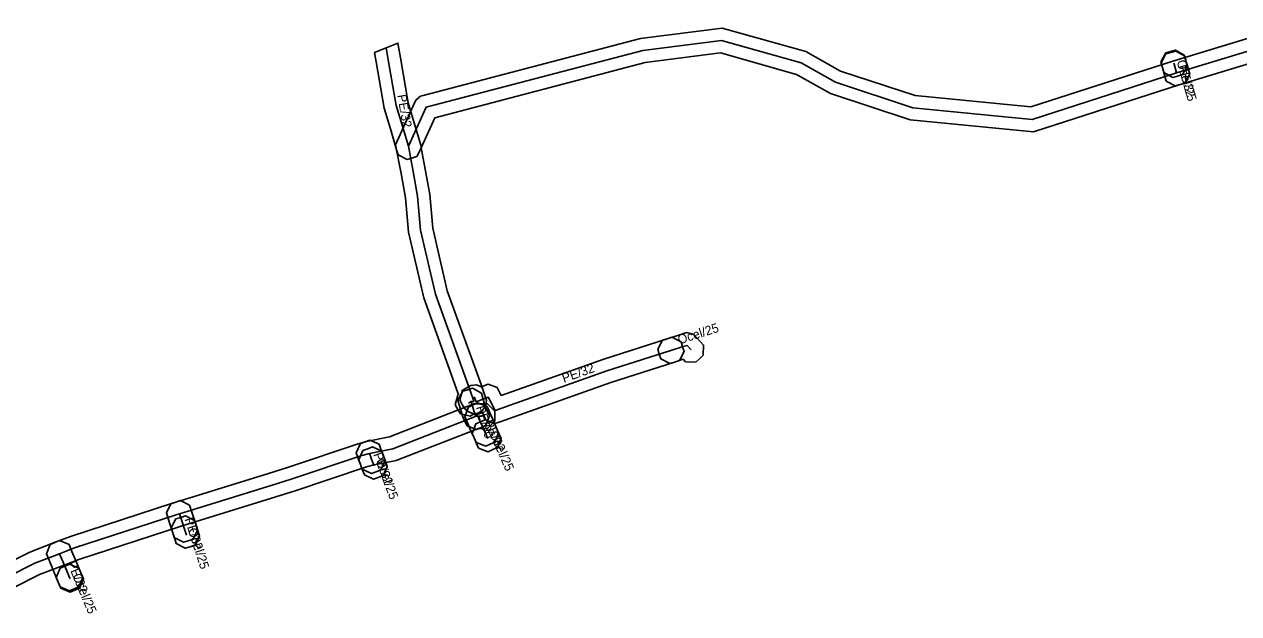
# Model space of a CAD drawing. Extents: x -677728 to -676939, y -1057290 to -1056960.
# Drawn here: x -677335.3 to -677236.2, y -1057106.7 to -1057058.6 of the extents above; entities that cross this region are included whole.
import ezdxf

# ---------------------------------------------------------------- set-up
doc = ezdxf.new("R2010")
doc.units = 0
for name, color, linetype in [('1', 7, 'Continuous'), ('24', 7, 'Continuous'), ('30', 7, 'Continuous')]:
    doc.layers.add(name, color=color, linetype=linetype)

msp = doc.modelspace()

# ---------------------------------------------------------------- linework, layer by layer
at = {"layer": '1'}
for points in [[(-677231.023, -1057060.492), (-677240.972, -1057063.495), (-677252.951, -1057067.366), (-677263.018, -1057066.374), (-677269.515, -1057064.24), (-677272.306, -1057062.67), (-677278.515, -1057060.928), (-677284.649, -1057061.714), (-677301.827, -1057066.207), (-677302.948, -1057068.666), (-677302.617, -1057070.408), (-677302.248, -1057072.467), (-677302, -1057075.232), (-677300.819, -1057080.327), (-677298.059, -1057087.981), (-677297.773, -1057088.779), (-677297.688, -1057089.045), (-677297.617, -1057089.268), (-677297.686, -1057089.73), (-677297.82, -1057089.922), (-677297.953, -1057090.114), (-677298.363, -1057090.339), (-677298.576, -1057090.348), (-677298.581, -1057090.351), (-677298.938, -1057090.562), (-677299.74, -1057090.356), (-677299.951, -1057089.999), (-677300.162, -1057089.642), (-677299.956, -1057088.84), (-677299.89, -1057088.801), (-677299.941, -1057088.659), (-677302.741, -1057080.893), (-677303.98, -1057075.548), (-677304.232, -1057072.733), (-677304.583, -1057070.772), (-677305.032, -1057068.414), (-677303.45, -1057064.945), (-677303.357, -1057064.74), (-677303.011, -1057064.45), (-677302.793, -1057064.393), (-677285.031, -1057059.746), (-677278.365, -1057058.892), (-677271.534, -1057060.81), (-677268.705, -1057062.4), (-677262.602, -1057064.406), (-677253.169, -1057065.334), (-677241.568, -1057061.585), (-677231.637, -1057058.588)], [(-677337.06, -1057102.732), (-677334.905, -1057101.644), (-677332.818, -1057100.846), (-677331.573, -1057100.367), (-677323.168, -1057097.639), (-677322.977, -1057097.577), (-677321.569, -1057097.126), (-677315.406, -1057095.225), (-677313.857, -1057094.738), (-677308.079, -1057092.816), (-677307.41, -1057092.618), (-677305.541, -1057092.246), (-677298.648, -1057089.56), (-677298.31, -1057089.56), (-677297.94, -1057089.56), (-677297.526, -1057089.56), (-677296.94, -1057090.146), (-677296.94, -1057090.56), (-677296.94, -1057090.974), (-677297.526, -1057091.56), (-677297.94, -1057091.56), (-677298.271, -1057091.56), (-677304.979, -1057094.174), (-677306.93, -1057094.562), (-677307.479, -1057094.724), (-677313.241, -1057096.642), (-677314.812, -1057097.135), (-677320.969, -1057099.034), (-677322.365, -1057099.481), (-677322.552, -1057099.541), (-677330.905, -1057102.253), (-677332.102, -1057102.714), (-677334.095, -1057103.476), (-677336.1, -1057104.488)]]:
    msp.add_lwpolyline(points, dxfattribs=at)
for points in [[(-677306.745, -1057060.884), (-677304.845, -1057060.124), (-677304.644, -1057061.323), (-677304.015, -1057064.981), (-677303.547, -1057066.538), (-677303.032, -1057068.252), (-677302.913, -1057068.649), (-677303.306, -1057069.379), (-677303.702, -1057069.498), (-677304.099, -1057069.617), (-677304.829, -1057069.224), (-677304.948, -1057068.828), (-677305.463, -1057067.114), (-677305.965, -1057065.439), (-677306.616, -1057061.657)], [(-677242.317, -1057062.521), (-677242.431, -1057062.123), (-677242.453, -1057062.046), (-677242.566, -1057061.648), (-677242.164, -1057060.923), (-677241.766, -1057060.809), (-677241.368, -1057060.696), (-677240.643, -1057061.098), (-677240.529, -1057061.496), (-677240.507, -1057061.573), (-677240.394, -1057061.971), (-677240.796, -1057062.696), (-677241.194, -1057062.81), (-677241.592, -1057062.923)], [(-677242.117, -1057063.214), (-677242.231, -1057062.816), (-677242.381, -1057062.295), (-677242.43, -1057062.125), (-677242.545, -1057061.727), (-677242.144, -1057061.002), (-677241.746, -1057060.887), (-677241.348, -1057060.772), (-677240.623, -1057061.173), (-677240.508, -1057061.571), (-677240.459, -1057061.741), (-677240.309, -1057062.264), (-677240.195, -1057062.662), (-677240.596, -1057063.387), (-677240.994, -1057063.501), (-677241.392, -1057063.615)], [(-677281.356, -1057086.123), (-677281.546, -1057085.919), (-677282.252, -1057086.145), (-677282.646, -1057086.271), (-677283.383, -1057085.892), (-677283.509, -1057085.498), (-677283.635, -1057085.104), (-677283.256, -1057084.367), (-677282.862, -1057084.241), (-677281.841, -1057083.914), (-677281.52, -1057083.82), (-677281.248, -1057083.741), (-677280.701, -1057083.892), (-677280.508, -1057084.099), (-677280.174, -1057084.458), (-677279.892, -1057084.761), (-677279.922, -1057085.589), (-677280.225, -1057085.871), (-677280.528, -1057086.153)], [(-677299.253, -1057090.121), (-677299.303, -1057089.978), (-677299.383, -1057089.956), (-677299.588, -1057089.596), (-677299.793, -1057089.236), (-677299.576, -1057088.437), (-677299.216, -1057088.232), (-677299.076, -1057088.152), (-677298.883, -1057088.041), (-677298.439, -1057088.005), (-677298.231, -1057088.083), (-677298.034, -1057088.156), (-677297.832, -1057088.078), (-677297.474, -1057087.939), (-677296.755, -1057088.212), (-677296.58, -1057088.554), (-677296.451, -1057088.805), (-677296.42, -1057088.866), (-677288.11, -1057085.922), (-677282.862, -1057084.241), (-677282.468, -1057084.115), (-677281.731, -1057084.494), (-677281.605, -1057084.888), (-677281.479, -1057085.282), (-677281.858, -1057086.019), (-677282.252, -1057086.145), (-677287.47, -1057087.818), (-677296.576, -1057091.043), (-677296.93, -1057091.168), (-677297.628, -1057090.891), (-677297.799, -1057090.557), (-677297.948, -1057090.268), (-677298.088, -1057090.322), (-677298.483, -1057090.476), (-677298.868, -1057090.298)], [(-677298.024, -1057088.684), (-677297.909, -1057089.082), (-677297.69, -1057089.84), (-677297.551, -1057090.142), (-677297.378, -1057090.519), (-677297.666, -1057091.296), (-677298.042, -1057091.469), (-677298.419, -1057091.642), (-677299.196, -1057091.354), (-677299.369, -1057090.978), (-677299.57, -1057090.54), (-677299.831, -1057089.638), (-677299.946, -1057089.24), (-677299.546, -1057088.514), (-677299.148, -1057088.399), (-677298.75, -1057088.284)], [(-677298.452, -1057092.715), (-677298.619, -1057092.336), (-677298.881, -1057091.742), (-677299.225, -1057090.964), (-677299.392, -1057090.585), (-677299.093, -1057089.813), (-677298.714, -1057089.645), (-677298.335, -1057089.478), (-677297.563, -1057089.777), (-677297.395, -1057090.156), (-677297.051, -1057090.934), (-677296.789, -1057091.528), (-677296.622, -1057091.907), (-677296.921, -1057092.68), (-677297.3, -1057092.847), (-677297.679, -1057093.014)], [(-677296.957, -1057091.149), (-677296.789, -1057091.528), (-677296.594, -1057091.969), (-677296.427, -1057092.348), (-677296.726, -1057093.12), (-677297.105, -1057093.288), (-677297.484, -1057093.455), (-677298.256, -1057093.156), (-677298.424, -1057092.777), (-677298.619, -1057092.336), (-677298.786, -1057091.957), (-677298.487, -1057091.185), (-677298.108, -1057091.017), (-677297.729, -1057090.85)], [(-677307.757, -1057094.888), (-677307.9, -1057094.499), (-677308.024, -1057094.164), (-677308.108, -1057093.937), (-677308.252, -1057093.548), (-677307.906, -1057092.796), (-677307.517, -1057092.652), (-677307.128, -1057092.508), (-677306.376, -1057092.854), (-677306.232, -1057093.243), (-677306.148, -1057093.47), (-677306.024, -1057093.807), (-677305.881, -1057094.196), (-677306.227, -1057094.948), (-677306.616, -1057095.091), (-677307.005, -1057095.234)], [(-677306.168, -1057093.417), (-677306.024, -1057093.806), (-677305.854, -1057094.266), (-677305.71, -1057094.655), (-677306.056, -1057095.407), (-677306.445, -1057095.551), (-677306.834, -1057095.695), (-677307.586, -1057095.349), (-677307.73, -1057094.96), (-677307.9, -1057094.5), (-677308.044, -1057094.111), (-677307.698, -1057093.359), (-677307.309, -1057093.215), (-677306.92, -1057093.071)], [(-677323.098, -1057100.467), (-677323.225, -1057100.073), (-677323.411, -1057099.495), (-677323.623, -1057098.835), (-677323.75, -1057098.441), (-677323.371, -1057097.704), (-677322.977, -1057097.577), (-677322.583, -1057097.45), (-677321.846, -1057097.829), (-677321.719, -1057098.223), (-677321.507, -1057098.883), (-677321.321, -1057099.461), (-677321.194, -1057099.855), (-677321.573, -1057100.592), (-677321.967, -1057100.719), (-677322.361, -1057100.846)], [(-677321.447, -1057099.068), (-677321.321, -1057099.462), (-677321.164, -1057099.952), (-677321.038, -1057100.346), (-677321.417, -1057101.083), (-677321.811, -1057101.209), (-677322.205, -1057101.335), (-677322.942, -1057100.956), (-677323.068, -1057100.562), (-677323.225, -1057100.072), (-677323.351, -1057099.678), (-677322.972, -1057098.941), (-677322.578, -1057098.815), (-677322.184, -1057098.689)], [(-677332.414, -1057104.486), (-677332.574, -1057104.104), (-677332.957, -1057103.187), (-677333.383, -1057102.165), (-677333.542, -1057101.783), (-677333.227, -1057101.016), (-677332.845, -1057100.857), (-677332.463, -1057100.698), (-677331.696, -1057101.013), (-677331.537, -1057101.395), (-677331.111, -1057102.417), (-677330.728, -1057103.332), (-677330.569, -1057103.714), (-677330.883, -1057104.481), (-677331.265, -1057104.641), (-677331.647, -1057104.8)], [(-677330.889, -1057102.95), (-677330.729, -1057103.332), (-677330.685, -1057103.437), (-677330.525, -1057103.819), (-677330.839, -1057104.585), (-677331.221, -1057104.745), (-677331.603, -1057104.905), (-677332.369, -1057104.591), (-677332.529, -1057104.209), (-677332.573, -1057104.104), (-677332.733, -1057103.722), (-677332.419, -1057102.956), (-677332.037, -1057102.796), (-677331.655, -1057102.636)]]:
    msp.add_lwpolyline(points, close=True, dxfattribs=at)
at = {"layer": '24'}
for points in [[(-677299.09, -1057089.49), (-677298.87, -1057089.36), (-677298.64, -1057089.35), (-677298.72, -1057089.1), (-677299, -1057088.32), (-677301.78, -1057080.61), (-677302.99, -1057075.39), (-677303.24, -1057072.6), (-677303.6, -1057070.59), (-677303.99, -1057068.54), (-677302.54, -1057065.36), (-677284.84, -1057060.73), (-677278.44, -1057059.91), (-677271.92, -1057061.74), (-677269.11, -1057063.32), (-677262.81, -1057065.39), (-677253.06, -1057066.35), (-677241.27, -1057062.54), (-677231.33, -1057059.54)], [(-677303.99, -1057068.54), (-677304.505, -1057066.826), (-677304.99, -1057065.21), (-677305.63, -1057061.49), (-677305.795, -1057060.504)], [(-677241.469, -1057061.848), (-677241.491, -1057061.771)], [(-677241.27, -1057062.54), (-677241.42, -1057062.018), (-677241.469, -1057061.848)], [(-677282.557, -1057085.193), (-677281.549, -1057084.87), (-677281.24, -1057084.78), (-677280.906, -1057085.139)], [(-677298.72, -1057089.1), (-677298.58, -1057089.02), (-677298.45, -1057089.39), (-677297.47, -1057089.01), (-677297.341, -1057089.262), (-677296.91, -1057090.1), (-677287.79, -1057086.87), (-677282.557, -1057085.193)], [(-677298.87, -1057089.36), (-677298.63, -1057090.19), (-677298.46, -1057090.56)], [(-677297.94, -1057090.56), (-677298.31, -1057090.56), (-677298.46, -1057090.56), (-677305.26, -1057093.21), (-677307.17, -1057093.59), (-677307.779, -1057093.77), (-677313.549, -1057095.69), (-677315.109, -1057096.18), (-677321.269, -1057098.08), (-677322.671, -1057098.529), (-677322.86, -1057098.59), (-677331.239, -1057101.31), (-677332.46, -1057101.78), (-677334.5, -1057102.56), (-677336.58, -1057103.61), (-677339.86, -1057105.55), (-677342.04, -1057104.6), (-677352.76, -1057100.9), (-677356.08, -1057100.3), (-677360.81, -1057098.32), (-677366.69, -1057096.31), (-677378.49, -1057092.57), (-677382.416, -1057091.152)], [(-677297.704, -1057091.932), (-677297.966, -1057091.338), (-677298.31, -1057090.56)], [(-677297.704, -1057091.932), (-677297.509, -1057092.373)], [(-677306.962, -1057094.153), (-677307.086, -1057093.817), (-677307.17, -1057093.59)], [(-677306.962, -1057094.153), (-677306.792, -1057094.613)], [(-677322.273, -1057099.767), (-677322.459, -1057099.189), (-677322.671, -1057098.529)], [(-677322.273, -1057099.767), (-677322.116, -1057100.257)], [(-677331.651, -1057103.718), (-677332.034, -1057102.802), (-677332.46, -1057101.78)], [(-677331.651, -1057103.718), (-677331.607, -1057103.823)]]:
    msp.add_lwpolyline(points, dxfattribs=at)

# ---------------------------------------------------------------- texts
at = {"layer": '30'}
for s, rotation, p in [('Ocel/25', 285.9454, (-677241.28, -1057061.61)), ('PE/32', 286.03234, (-677241.169, -1057061.994)), ('PE/32', 279.76177, (-677304.9, -1057064.371)), ('Ocel/25', 17.76736, (-677281.866, -1057084.708)), ('PE/32', 19.50245, (-677291.294, -1057087.84)), ('PE/90', 286.12758, (-677298.48, -1057089.819)), ('PE/32', 293.85307, (-677297.807, -1057091.046)), ('Ocel/25', 293.85391, (-677297.407, -1057091.953)), ('PE/32', 290.25646, (-677306.866, -1057093.671)), ('Ocel/25', 290.28256, (-677306.677, -1057094.183)), ('PE/32', 287.80765, (-677322.272, -1057098.948)), ('Ocel/25', 287.76588, (-677321.995, -1057099.812)), ('PE/32', 292.62783, (-677331.856, -1057102.549)), ('Ocel/25', 292.736, (-677331.429, -1057103.571))]:
    msp.add_text(s, height=0.75, rotation=rotation, dxfattribs=at).set_placement(p)

doc.saveas('drawing.dxf')
